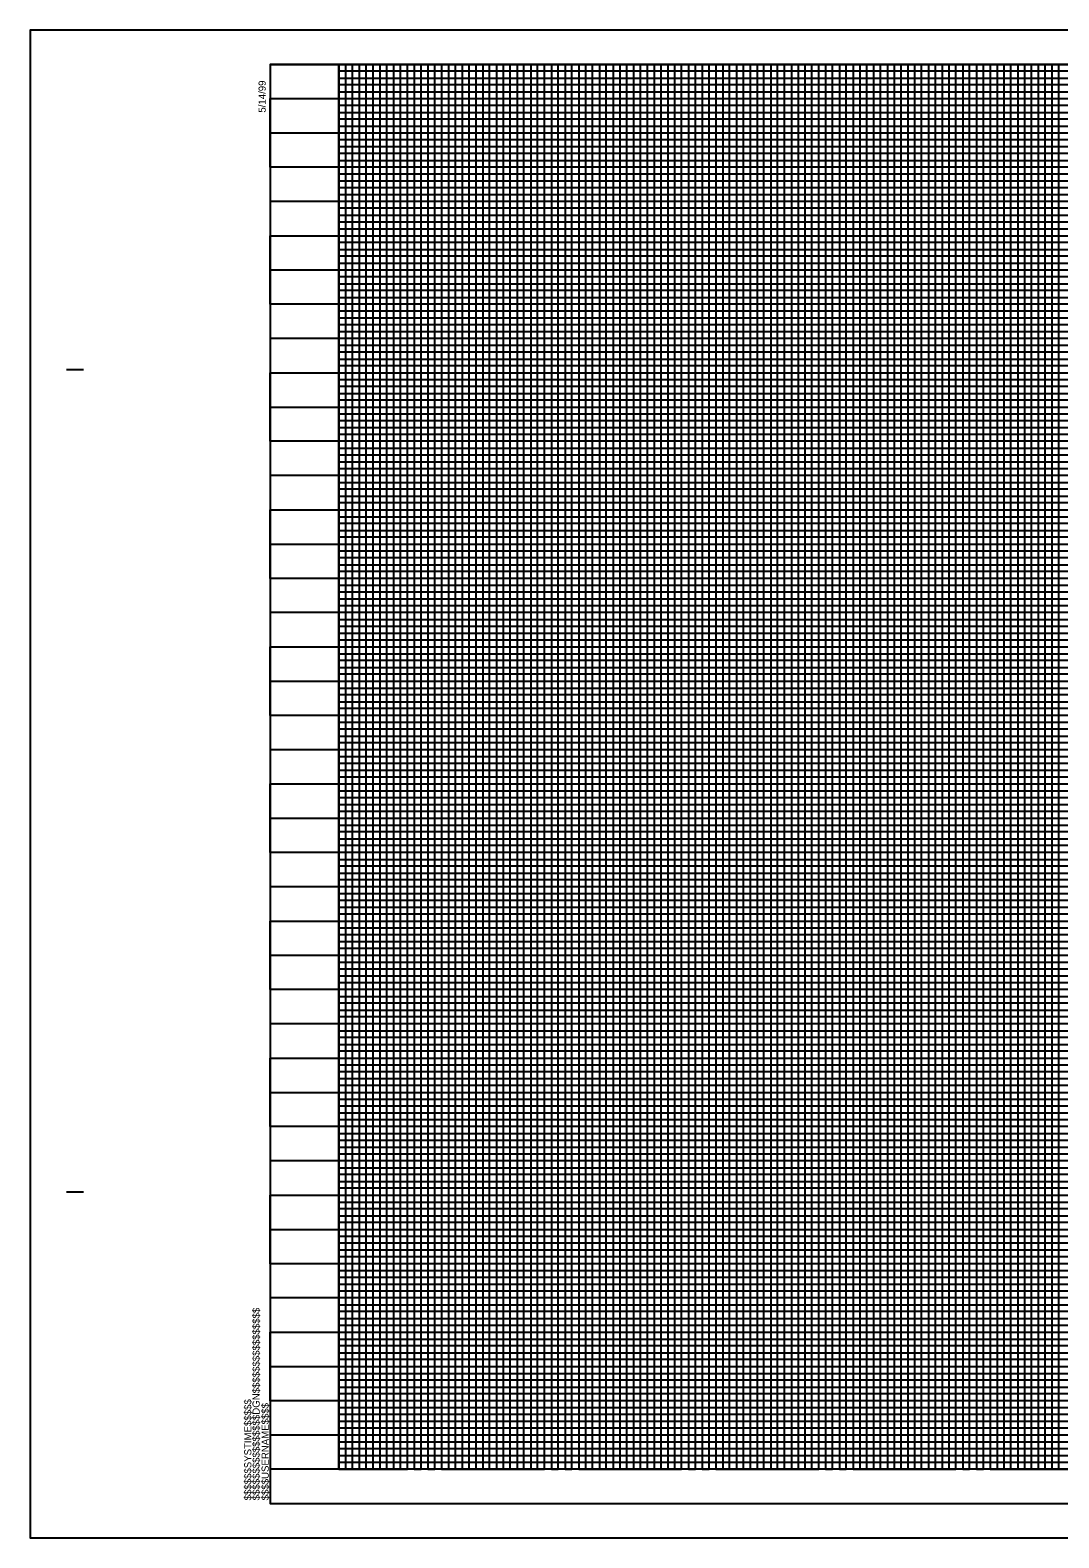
# Model space of a CAD drawing. Extents: x 573078 to 573131.9, y -55221.3 to -55195.5.
# Drawn here: x 573078.01 to 573093.01, y -55221.3 to -55199.3 of the extents above; entities that cross this region are included whole.
import ezdxf

# ---------------------------------------------------------------- set-up
doc = ezdxf.new("R2010")
doc.units = 0
for name, color, linetype in [('Sheet Clip Boundary CELL', 7, 'Continuous'), ('Sheet Plot Border Inside CELL', 7, 'Continuous'), ('Sheet Profile CELL', 7, 'Continuous'), ('Sheet Profile Grid Major CELL', 7, 'Continuous'), ('Sheet Profile Grid Middle CELL', 7, 'Continuous'), ('Sheet Profile Grid Minor CELL', 7, 'Continuous')]:
    doc.layers.add(name, color=color, linetype=linetype)

msp = doc.modelspace()

# ---------------------------------------------------------------- linework, layer by layer
at = {"layer": 'Sheet Clip Boundary CELL'}
msp.add_lwpolyline([(573082.514, -55199.798), (573107.514, -55199.798), (573107.514, -55203.019), (573110.514, -55203.019), (573110.514, -55220.298), (573082.514, -55220.298)], close=True, dxfattribs=at)
at = {"layer": 'Sheet Plot Border Inside CELL'}
msp.add_lwpolyline([(573112.014, -55199.298), (573078.014, -55199.298), (573078.014, -55221.298), (573112.014, -55221.298)], close=True, dxfattribs=at)
at = {"layer": 'Sheet Profile CELL'}
for p, q in [((573078.544, -55204.248), (573078.794, -55204.248)), ((573078.544, -55216.248), (573078.794, -55216.248)), ((573111.514, -55220.298), (573081.514, -55220.298)), ((573081.514, -55220.798), (573081.514, -55220.798)), ((573081.514, -55220.798), (573081.514, -55220.798)), ((573081.514, -55220.798), (573081.514, -55220.798)), ((573081.514, -55220.798), (573081.514, -55220.798)), ((573081.514, -55220.798), (573081.514, -55220.798)), ((573081.514, -55220.798), (573081.514, -55220.798))]:
    msp.add_line(p, q, dxfattribs=at)
msp.add_lwpolyline([(573111.514, -55199.798), (573081.514, -55199.798), (573081.514, -55220.798), (573111.514, -55220.798)], close=True, dxfattribs=at)
msp.add_lwpolyline([(573082.264, -55220.798), (573082.264, -55220.798)], dxfattribs=at)
at = {"layer": 'Sheet Profile Grid Major CELL'}
for points in [[(573081.514, -55199.798), (573082.514, -55199.798), (573082.514, -55220.298), (573083.514, -55220.298), (573083.514, -55199.798), (573084.514, -55199.798), (573084.514, -55220.298), (573085.514, -55220.298), (573085.514, -55199.798), (573086.514, -55199.798), (573086.514, -55220.298), (573087.514, -55220.298), (573087.514, -55199.798), (573088.514, -55199.798), (573088.514, -55220.298), (573089.514, -55220.298), (573089.514, -55199.798), (573090.514, -55199.798), (573090.514, -55220.298), (573091.514, -55220.298), (573091.514, -55199.798), (573092.514, -55199.798), (573092.514, -55220.298), (573093.514, -55220.298)], [(573107.514, -55201.298), (573081.514, -55201.298), (573081.514, -55200.298), (573104.513, -55200.298)], [(573111.514, -55203.298), (573081.514, -55203.298), (573081.514, -55202.298), (573107.514, -55202.298)], [(573111.514, -55205.298), (573081.514, -55205.298), (573081.514, -55204.298), (573111.514, -55204.298)], [(573111.514, -55207.298), (573081.514, -55207.298), (573081.514, -55206.298), (573111.514, -55206.298)], [(573111.514, -55209.298), (573081.514, -55209.298), (573081.514, -55208.298), (573111.514, -55208.298)], [(573111.514, -55211.298), (573081.514, -55211.298), (573081.514, -55210.298), (573111.514, -55210.298)], [(573111.514, -55213.298), (573081.514, -55213.298), (573081.514, -55212.298), (573111.514, -55212.298)], [(573111.514, -55215.298), (573081.514, -55215.298), (573081.514, -55214.298), (573111.514, -55214.298)], [(573111.514, -55217.298), (573081.514, -55217.298), (573081.514, -55216.298), (573111.514, -55216.298)], [(573111.514, -55219.298), (573081.514, -55219.298), (573081.514, -55218.298), (573111.514, -55218.298)]]:
    msp.add_lwpolyline(points, dxfattribs=at)
at = {"layer": 'Sheet Profile Grid Middle CELL'}
for points in [[(573083.014, -55220.298), (573083.014, -55199.798), (573084.014, -55199.798), (573084.014, -55220.298), (573085.014, -55220.298), (573085.014, -55199.798), (573086.014, -55199.798), (573086.014, -55220.298), (573087.014, -55220.298), (573087.014, -55199.798), (573088.014, -55199.798), (573088.014, -55220.298), (573089.014, -55220.298), (573089.014, -55199.798), (573090.014, -55199.798), (573090.014, -55220.298), (573091.014, -55220.298), (573091.014, -55199.798), (573092.014, -55199.798), (573092.014, -55220.298), (573093.014, -55220.298), (573093.014, -55199.798), (573094.014, -55199.798)], [(573081.514, -55200.798), (573104.513, -55200.798)], [(573107.514, -55201.798), (573081.514, -55201.798), (573081.514, -55202.798), (573107.514, -55202.798)], [(573111.514, -55203.798), (573081.514, -55203.798), (573081.514, -55204.798), (573111.514, -55204.798)], [(573111.514, -55205.798), (573081.514, -55205.798), (573081.514, -55206.798), (573111.514, -55206.798)], [(573111.514, -55207.798), (573081.514, -55207.798), (573081.514, -55208.798), (573111.514, -55208.798)], [(573111.514, -55209.798), (573081.514, -55209.798), (573081.514, -55210.798), (573111.514, -55210.798)], [(573111.514, -55211.798), (573081.514, -55211.798), (573081.514, -55212.798), (573111.514, -55212.798)], [(573111.514, -55213.798), (573081.514, -55213.798), (573081.514, -55214.798), (573111.514, -55214.798)], [(573111.514, -55215.798), (573081.514, -55215.798), (573081.514, -55216.798), (573111.514, -55216.798)], [(573111.514, -55217.798), (573081.514, -55217.798), (573081.514, -55218.798), (573111.514, -55218.798)], [(573111.514, -55219.798), (573081.514, -55219.798)]]:
    msp.add_lwpolyline(points, dxfattribs=at)
at = {"layer": 'Sheet Profile Grid Minor CELL'}
for p, q in [((573110.514, -55203.398), (573082.514, -55203.398)), ((573082.514, -55203.398), (573082.514, -55203.498)), ((573082.514, -55203.498), (573110.514, -55203.498)), ((573110.514, -55203.898), (573082.514, -55203.898))]:
    msp.add_line(p, q, dxfattribs=at)
for points in [[(573082.614, -55199.798), (573082.714, -55199.798), (573082.814, -55199.798), (573082.914, -55199.798), (573083.114, -55199.798), (573082.453, -55199.798), (573082.553, -55199.798), (573081.714, -55199.798), (573081.814, -55199.798), (573081.914, -55199.798), (573082.114, -55199.798), (573082.214, -55199.798), (573082.314, -55199.798), (573082.414, -55199.798), (573082.614, -55199.798), (573082.614, -55220.298), (573082.714, -55220.298), (573082.714, -55199.798), (573082.814, -55199.798), (573082.814, -55220.298), (573082.914, -55220.298), (573082.914, -55199.798), (573083.114, -55199.798), (573083.114, -55220.298), (573083.214, -55220.298), (573083.214, -55199.798), (573083.314, -55199.798), (573083.314, -55220.298), (573083.414, -55220.298), (573083.414, -55199.798), (573083.614, -55199.798), (573083.614, -55220.298), (573083.714, -55220.298), (573083.714, -55199.798), (573083.814, -55199.798), (573083.814, -55220.298), (573083.914, -55220.298), (573083.914, -55199.798), (573084.114, -55199.798), (573084.114, -55220.298), (573084.214, -55220.298), (573084.214, -55199.798), (573084.314, -55199.798), (573084.314, -55220.298), (573084.414, -55220.298), (573084.414, -55199.798), (573084.614, -55199.798), (573084.614, -55220.298), (573084.714, -55220.298), (573084.714, -55199.798), (573084.814, -55199.798), (573084.814, -55220.298), (573084.914, -55220.298), (573084.914, -55199.798), (573085.114, -55199.798), (573085.114, -55220.298), (573085.214, -55220.298), (573085.214, -55199.798), (573085.314, -55199.798), (573085.314, -55220.298), (573085.414, -55220.298), (573085.414, -55199.798), (573085.614, -55199.798), (573085.614, -55220.298), (573085.714, -55220.298), (573085.714, -55199.798), (573085.814, -55199.798), (573085.814, -55220.298)], [(573104.513, -55199.898), (573082.514, -55199.898), (573082.514, -55199.998), (573104.513, -55199.998)], [(573085.814, -55220.298), (573085.914, -55220.298), (573085.914, -55199.798), (573086.114, -55199.798), (573086.114, -55220.298), (573086.214, -55220.298), (573086.214, -55199.798), (573086.314, -55199.798), (573086.314, -55220.298), (573086.414, -55220.298), (573086.414, -55199.798), (573086.614, -55199.798), (573086.614, -55220.298), (573086.714, -55220.298), (573086.714, -55199.798), (573086.714, -55199.798), (573086.814, -55199.798), (573086.814, -55220.298), (573086.914, -55220.298), (573086.914, -55199.798), (573087.114, -55199.798), (573087.114, -55220.298), (573087.214, -55220.298), (573087.214, -55199.798), (573087.314, -55199.798), (573087.314, -55220.298), (573087.414, -55220.298), (573087.414, -55199.798), (573087.614, -55199.798), (573087.614, -55220.298), (573087.714, -55220.298), (573087.714, -55199.798), (573087.814, -55199.798), (573087.814, -55220.298), (573087.914, -55220.298), (573087.914, -55199.798), (573088.114, -55199.798), (573088.114, -55220.298), (573088.214, -55220.298), (573088.214, -55199.798), (573088.314, -55199.798), (573088.314, -55220.298), (573088.414, -55220.298), (573088.414, -55199.798), (573088.614, -55199.798), (573088.614, -55220.298), (573088.714, -55220.298), (573088.714, -55199.798), (573088.814, -55199.798), (573088.814, -55220.298), (573088.914, -55220.298), (573088.914, -55199.798), (573089.114, -55199.798), (573089.114, -55220.298), (573089.414, -55220.298), (573089.414, -55199.798), (573089.614, -55199.798), (573089.614, -55220.298), (573089.714, -55220.298), (573089.714, -55199.798), (573089.814, -55199.798), (573089.814, -55220.298), (573089.914, -55220.298), (573089.914, -55199.798), (573090.114, -55199.798), (573090.114, -55220.298), (573090.214, -55220.298), (573090.214, -55199.798), (573090.314, -55199.798), (573090.314, -55220.298), (573090.414, -55220.298), (573090.414, -55199.798), (573090.614, -55199.798), (573090.614, -55220.298), (573090.714, -55220.298), (573090.714, -55199.798), (573090.814, -55199.798), (573090.814, -55220.298), (573090.914, -55220.298), (573090.914, -55199.798), (573091.114, -55199.798), (573091.114, -55220.298), (573091.214, -55220.298), (573091.214, -55199.798), (573091.314, -55199.798), (573091.314, -55220.298), (573091.414, -55220.298), (573091.414, -55199.798), (573091.614, -55199.798), (573091.614, -55220.298), (573091.714, -55220.298), (573091.714, -55199.798), (573091.814, -55199.798), (573091.814, -55220.298), (573091.914, -55220.298), (573091.914, -55199.798), (573092.114, -55199.798), (573092.114, -55220.298)], [(573089.214, -55199.798), (573089.214, -55220.298), (573089.314, -55220.298), (573089.314, -55199.798)], [(573089.214, -55199.81), (573089.214, -55220.298), (573089.314, -55220.298), (573089.314, -55199.81)], [(573092.214, -55199.798), (573092.214, -55220.298), (573092.314, -55220.298), (573092.314, -55199.798), (573092.414, -55199.798), (573092.414, -55220.298), (573092.614, -55220.298), (573092.614, -55199.798), (573092.714, -55199.798), (573092.714, -55220.298), (573092.814, -55220.298), (573092.814, -55199.798), (573092.914, -55199.798), (573092.914, -55220.298)], [(573104.513, -55200.098), (573082.514, -55200.098), (573082.514, -55200.198), (573104.513, -55200.198)], [(573104.513, -55200.398), (573082.514, -55200.398), (573082.514, -55200.498), (573104.513, -55200.498)], [(573104.513, -55200.598), (573082.514, -55200.598), (573082.514, -55200.698), (573104.513, -55200.698)], [(573104.513, -55200.898), (573082.514, -55200.898), (573082.514, -55200.998), (573104.513, -55200.998)], [(573104.513, -55201.098), (573082.514, -55201.098), (573082.514, -55201.198), (573104.513, -55201.198)], [(573107.514, -55201.398), (573082.514, -55201.398), (573082.514, -55201.498), (573107.514, -55201.498)], [(573107.514, -55201.598), (573082.514, -55201.598), (573082.514, -55201.698), (573107.514, -55201.698)], [(573107.514, -55201.898), (573082.514, -55201.898), (573082.514, -55201.998), (573107.514, -55201.998)], [(573107.514, -55202.098), (573082.514, -55202.098), (573082.514, -55202.198), (573107.514, -55202.198)], [(573107.514, -55202.398), (573082.514, -55202.398), (573082.514, -55202.498), (573107.514, -55202.498)], [(573107.514, -55202.598), (573082.514, -55202.598), (573082.514, -55202.598), (573082.514, -55202.998), (573107.514, -55202.998)], [(573082.514, -55202.698), (573107.514, -55202.698)], [(573107.514, -55202.898), (573082.514, -55202.898)], [(573110.514, -55203.098), (573082.514, -55203.098), (573082.514, -55203.198), (573110.514, -55203.198)], [(573110.514, -55203.598), (573082.514, -55203.598), (573082.514, -55203.698), (573110.514, -55203.698)], [(573110.514, -55203.998), (573082.514, -55203.998), (573082.514, -55204.098), (573110.514, -55204.098)], [(573110.514, -55204.198), (573082.514, -55204.198)], [(573082.514, -55204.398), (573110.514, -55204.398)], [(573110.514, -55204.498), (573082.514, -55204.498), (573082.514, -55204.598), (573110.514, -55204.598)], [(573110.514, -55204.698), (573082.514, -55204.698), (573082.514, -55204.898), (573110.514, -55204.898)], [(573110.514, -55204.998), (573082.514, -55204.998), (573082.514, -55205.098), (573110.514, -55205.098)], [(573110.514, -55205.198), (573082.514, -55205.198), (573082.514, -55205.398), (573110.514, -55205.398)], [(573110.514, -55205.498), (573082.514, -55205.498), (573082.514, -55205.598), (573110.514, -55205.598)], [(573110.514, -55205.698), (573082.514, -55205.698), (573082.514, -55205.898), (573110.514, -55205.898)], [(573110.514, -55205.998), (573082.514, -55205.998), (573082.514, -55206.098), (573110.514, -55206.098)], [(573110.514, -55206.198), (573082.514, -55206.198), (573082.514, -55206.398), (573110.514, -55206.398)], [(573110.514, -55206.498), (573082.514, -55206.498), (573082.514, -55206.598), (573110.514, -55206.598)], [(573110.514, -55206.698), (573082.514, -55206.698), (573082.514, -55206.898), (573110.514, -55206.898)], [(573110.514, -55206.998), (573082.514, -55206.998), (573082.514, -55207.098), (573110.514, -55207.098)], [(573110.514, -55207.198), (573082.514, -55207.198), (573082.514, -55207.398), (573110.514, -55207.398)], [(573110.514, -55207.498), (573082.514, -55207.498), (573082.514, -55207.598), (573110.514, -55207.598)], [(573110.514, -55207.698), (573082.514, -55207.698), (573082.514, -55207.898), (573110.514, -55207.898)], [(573110.514, -55207.998), (573082.514, -55207.998), (573082.514, -55208.098), (573110.514, -55208.098)], [(573110.514, -55208.198), (573082.514, -55208.198), (573082.514, -55208.398), (573110.514, -55208.398)], [(573110.514, -55208.498), (573082.514, -55208.498), (573082.514, -55208.598), (573110.514, -55208.598)], [(573110.514, -55208.698), (573082.514, -55208.698), (573082.514, -55208.898), (573110.514, -55208.898)], [(573110.514, -55208.998), (573082.514, -55208.998), (573082.514, -55209.098), (573110.514, -55209.098)], [(573110.514, -55209.198), (573082.514, -55209.198), (573082.514, -55209.398), (573110.514, -55209.398)], [(573110.514, -55209.498), (573082.514, -55209.498), (573082.514, -55209.598), (573110.514, -55209.598)], [(573110.514, -55209.698), (573082.514, -55209.698), (573082.514, -55209.898), (573110.514, -55209.898)], [(573110.514, -55209.998), (573082.514, -55209.998), (573082.514, -55210.098), (573110.514, -55210.098)], [(573110.514, -55210.198), (573082.514, -55210.198)], [(573082.514, -55210.398), (573110.514, -55210.398)], [(573110.514, -55210.498), (573082.514, -55210.498), (573082.514, -55210.598), (573110.514, -55210.598)], [(573110.514, -55210.698), (573082.514, -55210.698), (573082.514, -55210.898), (573110.514, -55210.898)], [(573110.514, -55210.998), (573082.514, -55210.998), (573082.514, -55211.098), (573110.514, -55211.098)], [(573110.514, -55211.198), (573082.514, -55211.198), (573082.514, -55211.398), (573110.514, -55211.398)], [(573110.514, -55211.498), (573082.514, -55211.498), (573082.514, -55211.598), (573110.514, -55211.598)], [(573110.514, -55211.698), (573082.514, -55211.698), (573082.514, -55211.898), (573110.514, -55211.898)], [(573110.514, -55211.998), (573082.514, -55211.998), (573082.514, -55212.098), (573110.514, -55212.098)], [(573110.514, -55212.198), (573082.514, -55212.198), (573082.514, -55212.398), (573110.514, -55212.398)], [(573110.514, -55212.498), (573082.514, -55212.498), (573082.514, -55212.598), (573110.514, -55212.598)], [(573110.514, -55212.698), (573082.514, -55212.698), (573082.514, -55212.898), (573110.514, -55212.898)], [(573110.514, -55212.998), (573082.514, -55212.998), (573082.514, -55213.098), (573110.514, -55213.098)], [(573110.514, -55213.198), (573082.514, -55213.198), (573082.514, -55213.398), (573110.514, -55213.398)], [(573110.514, -55213.498), (573082.514, -55213.498), (573082.514, -55213.598), (573110.514, -55213.598)], [(573110.514, -55213.698), (573082.514, -55213.698), (573082.514, -55213.898), (573110.514, -55213.898)], [(573110.514, -55213.998), (573082.514, -55213.998), (573082.514, -55214.098), (573110.514, -55214.098)], [(573110.514, -55214.198), (573082.514, -55214.198), (573082.514, -55214.398), (573110.514, -55214.398)], [(573110.514, -55214.498), (573082.514, -55214.498), (573082.514, -55214.598), (573110.514, -55214.598)], [(573110.514, -55214.698), (573082.514, -55214.698), (573082.514, -55214.898), (573110.514, -55214.898)], [(573110.514, -55214.998), (573082.514, -55214.998), (573082.514, -55215.098), (573110.514, -55215.098)], [(573110.514, -55215.198), (573082.514, -55215.198), (573082.514, -55215.398), (573110.514, -55215.398)], [(573110.514, -55215.498), (573082.514, -55215.498), (573082.514, -55215.598), (573110.514, -55215.598)], [(573110.514, -55215.698), (573082.514, -55215.698), (573082.514, -55215.898), (573110.514, -55215.898)], [(573110.514, -55215.998), (573082.514, -55215.998), (573082.514, -55216.098), (573110.514, -55216.098)], [(573110.514, -55216.198), (573082.514, -55216.198)], [(573082.514, -55216.398), (573110.514, -55216.398)], [(573110.514, -55216.498), (573082.514, -55216.498), (573082.514, -55216.598), (573110.514, -55216.598)], [(573110.514, -55216.698), (573082.514, -55216.698)], [(573082.514, -55216.898), (573110.514, -55216.898)], [(573110.514, -55216.998), (573082.514, -55216.998), (573082.514, -55217.098), (573110.514, -55217.098)], [(573110.514, -55217.198), (573082.514, -55217.198), (573082.514, -55217.398), (573110.514, -55217.398)], [(573110.514, -55217.498), (573082.514, -55217.498), (573082.514, -55217.598), (573110.514, -55217.598)], [(573110.514, -55217.698), (573082.514, -55217.698), (573082.514, -55217.898), (573110.514, -55217.898)], [(573110.514, -55217.998), (573082.514, -55217.998), (573082.514, -55218.098), (573110.514, -55218.098)], [(573110.514, -55218.198), (573082.514, -55218.198), (573082.514, -55218.398), (573110.514, -55218.398)], [(573110.514, -55218.498), (573082.514, -55218.498), (573082.514, -55218.598), (573110.514, -55218.598)], [(573110.514, -55218.698), (573082.514, -55218.698), (573082.514, -55218.898), (573110.514, -55218.898)], [(573110.514, -55218.998), (573082.514, -55218.998), (573082.514, -55219.098), (573110.514, -55219.098)], [(573110.514, -55219.198), (573082.514, -55219.198), (573082.514, -55219.398), (573110.514, -55219.398)], [(573110.514, -55219.498), (573082.514, -55219.498), (573082.514, -55219.598), (573110.514, -55219.598)], [(573110.514, -55219.698), (573082.514, -55219.698), (573082.514, -55219.898), (573110.514, -55219.898)], [(573110.514, -55219.998), (573082.514, -55219.998), (573082.514, -55220.098), (573110.514, -55220.098)], [(573110.514, -55220.198), (573082.514, -55220.198)]]:
    msp.add_lwpolyline(points, dxfattribs=at)

# ---------------------------------------------------------------- texts
at = {"layer": 'Sheet Profile CELL'}
for s, p in [('5/14/99', (573081.449, -55200.502)), ('$$$$$$$$$$$$$$$$DGN$$$$$$$$$$$$$$$$', (573081.361, -55220.751)), ('$$$$$$SYSTIME$$$$$', (573081.24, -55220.751)), ('$$$$USERNAME$$$$', (573081.493, -55220.751))]:
    msp.add_text(s, height=0.105, rotation=90, dxfattribs=at).set_placement(p)

doc.saveas('drawing.dxf')
